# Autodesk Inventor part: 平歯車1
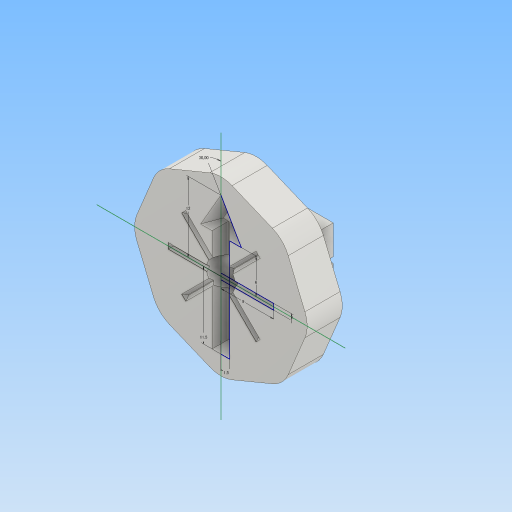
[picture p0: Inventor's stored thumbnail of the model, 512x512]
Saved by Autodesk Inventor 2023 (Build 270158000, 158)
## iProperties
CustomPartVersion: 1
Created: 2024-01
Part Number: 平歯車1
Material: Steel
Document SubType Name: Modeling
Designer: kumagai
Categories: <?xml version="1.0" encoding="UTF-16"?> <MemberInstance><Categories><FamilyTemplate><FamilyTemplateParameter ValueType="xs:double" Id="1" ObjectReferenceKey="da
Density: 1 g/cm^3
Appearance: Steel
Author: kumagai
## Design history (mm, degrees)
sketch "スケッチ3"
  geometry: L1 (0, 4.04)-(0, -7.09) reference; L2 (-10.08, 0)-(10.08, 0) reference; L3 (-7.2, -0.5)-(7.2, -0.5); L4 (7.2, -0.5)-(7.2, -5.5); L5 (7.2, -5.5)-(-7.2, -5.5); L6 (-7.2, -5.5)-(-7.2, -0.5); C1 r 2.45 at (0, 0); 3 further points
  constraints: 8 end point, 1 centre point, 1 coincident, 1 other
  dimensions: "d54" = 0.5 distance between parallel lines of L2 L3; "d55" = 7.2 distance between parallel lines of L6 L1; "d56" = 5.5 distance between parallel lines of L2 L5; "d59" = 4.9 diameter of C1
extrude "押し出し2" join sketch "スケッチ3" distance "d57" = 6; taper "d58" = 0 deg
sketch "スケッチ4"
  geometry: L1 (0, -5.52)-(0, 0.92) reference; L2 (-10.22, 0)-(10.22, 0) reference; C1 r 1.6 at (4.2, -3); C2 r 1.6 at (-4.2, -3); 1 further point
  constraints: 2 centre point, 1 other
  dimensions: "d60" = 3.2 diameter of C1; "d61" = 3 distance from line of L2 C1.centre; "d62" = 4.2 distance from line of L1 C1.centre
extrude "押し出し3" cut sketch "スケッチ4" extent not by distance; stored distance "d63" = 0; taper "d64" = 0 deg
pattern_circular "円形状パターン1" dims angle "d66" = 360 deg
sketch "スケッチ6"
  geometry: L1 (0, 27.276)-(0, -27.276) reference; L2 (-27.276, 0)-(27.276, 0) reference; L3 (0, -15.153)-(-10.715, -10.715); L4 (-10.715, -10.715)-(-15.153, 0); L5 (-15.153, 0)-(-10.715, 10.715); L6 (-10.715, 10.715)-(0, 15.153); L7 (0, 15.153)-(10.715, 10.715); L8 (10.715, 10.715)-(15.153, 0); L9 (15.153, 0)-(10.715, -10.715); L10 (10.715, -10.715)-(0, -15.153); C1 r 2.45 at (0, 0); 2 further points
  constraints: 16 end point, 2 coincident, 1 centre point, 1 point on line, 17 other
  dimensions: "d85" = 4.9 diameter of C1; "d86" = 28 distance between parallel lines of L7 L3
extrude "押し出し4" join sketch "スケッチ6" distance "d87" = 6; taper "d88" = 0 deg
fillet "フィレット1" dims "d89" = 5
sketch "スケッチ7"
  geometry: L1 (0, 21.215)-(0, -21.215) reference; L2 (-21.215, 0)-(21.215, 0) reference; L3 (0, 12)-(3.464, 6); L4 (3.464, 6)-(1.5, 6); L5 (1.5, 6)-(1.5, -11.5); L6 (1.5, -11.5)-(0, -11.5); L7 (0, 0.5)-(9, 0.5); L8 (9, 0.5)-(9, -0.5); L9 (9, -0.5)-(0, -0.5); 3 further points
  constraints: 14 end point, 4 point on line, 1 horizontal, 1 other
  dimensions: "d90" = 1.5 distance between parallel lines of L5 L1; "d91" = 12 distance from line of L3.start L2; "d92" = 30 deg angle of L1 L3; "d93" = 6 distance between parallel lines of L2 L4; "d99" = 1 distance between parallel lines of L9 L7; "d100" = 9 distance between parallel lines of L1 L8; "d109" = 11.5 distance between parallel lines of L6 L2
extrude "押し出し5" cut sketch "スケッチ7" distance "d94" = 1.4; taper "d95" = 0 deg
mirror "ミラー1"
chamfer "面取り4" distance "d96" = 1.4; stored, may be unused: second distance "d97" = 2, angle "d98" = 45 deg
extrude "押し出し6" cut sketch "スケッチ7" distance "d101" = 0.5; taper "d102" = 0 deg
chamfer "面取り5" distance "d103" = 0.45; stored, may be unused: second distance "d104" = 2, angle "d105" = 45 deg
pattern_circular "円形状パターン2" dims angle "d107" = 90 deg
mirror "ミラー2"
body "Solid1"
